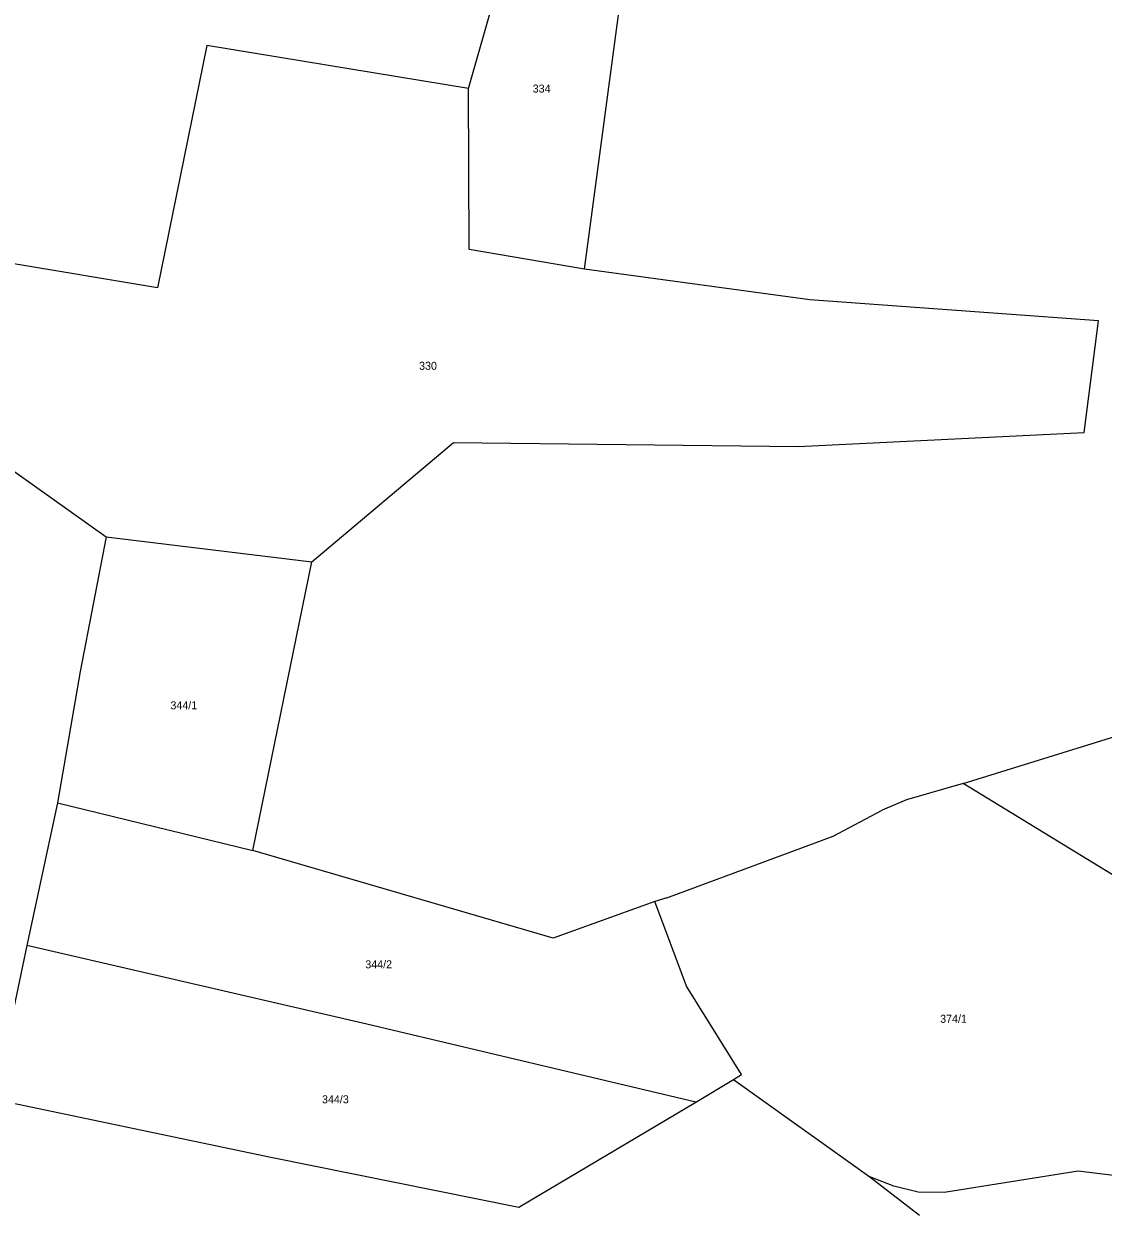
# Model space of a CAD drawing. Extents: x -791548 to -789311, y -1142631 to -1140855.
# Drawn here: x -790982.6 to -790753.3, y -1142211.2 to -1141959 of the extents above; entities that cross this region are included whole.
import ezdxf
from ezdxf.enums import TextEntityAlignment as Align

# ---------------------------------------------------------------- set-up
doc = ezdxf.new("R2010")
doc.units = 0
doc.header["$LTSCALE"] = 0.68
doc.layers.add('1', color=7, linetype='Continuous', lineweight=25)
doc.layers.add('2', color=7, linetype='Continuous')

msp = doc.modelspace()

# ---------------------------------------------------------------- linework, layer by layer
at = {"layer": '1'}
for p, q in [((-790888.15, -1141972.78), (-790875.94, -1141930.15)), ((-790863.48, -1142011.16), (-790853.52, -1141936.36)), ((-790943.74, -1141963.65), (-790954.25, -1142015.12)), ((-790888.15, -1141972.78), (-790943.74, -1141963.65)), ((-790887.96, -1142006.94), (-790888.15, -1141972.78)), ((-790863.48, -1142011.16), (-790887.96, -1142006.94)), ((-790954.25, -1142015.12), (-790985.61, -1142009.88)), ((-790815.6, -1142017.65), (-790863.48, -1142011.16)), ((-790754.26, -1142022.12), (-790815.6, -1142017.65)), ((-790757.29, -1142045.83), (-790754.26, -1142022.12)), ((-790818.07, -1142048.8), (-790757.29, -1142045.83)), ((-790994.07, -1142047.46), (-790965.09, -1142067.97)), ((-790921.39, -1142073.27), (-790891.29, -1142047.92)), ((-790891.29, -1142047.92), (-790818.07, -1142048.8)), ((-790965.09, -1142067.97), (-790970.68, -1142096.58)), ((-790965.09, -1142067.97), (-790921.39, -1142073.27)), ((-790933.96, -1142134.58), (-790921.39, -1142073.27)), ((-790970.68, -1142096.58), (-790975.45, -1142124.47)), ((-790783.03, -1142120.37), (-790726.36, -1142102.85)), ((-790783.03, -1142120.37), (-790795.07, -1142123.83)), ((-790750.26, -1142140.45), (-790783.03, -1142120.37)), ((-790975.45, -1142124.47), (-790981.99, -1142154.78)), ((-790975.45, -1142124.47), (-790933.96, -1142134.58)), ((-790795.07, -1142123.83), (-790800.24, -1142126.07)), ((-790810.64, -1142131.54), (-790800.24, -1142126.07)), ((-790845.97, -1142144.69), (-790810.64, -1142131.54)), ((-790870.15, -1142153.22), (-790933.96, -1142134.58)), ((-790845.97, -1142144.69), (-790848.57, -1142145.44)), ((-790848.57, -1142145.44), (-790870.15, -1142153.22)), ((-790841.8, -1142163.43), (-790848.57, -1142145.44)), ((-790981.99, -1142154.78), (-790988.86, -1142187.43)), ((-790909.71, -1142171.49), (-790981.99, -1142154.78)), ((-790830.16, -1142182.21), (-790841.8, -1142163.43)), ((-790839.81, -1142188.08), (-790909.71, -1142171.49)), ((-790831.84, -1142183.23), (-790830.16, -1142182.21)), ((-790839.81, -1142188.08), (-790831.84, -1142183.23)), ((-790831.84, -1142183.23), (-790802.84, -1142203.93)), ((-790988.86, -1142187.43), (-790930.11, -1142199.76)), ((-790877.41, -1142210.38), (-790839.81, -1142188.08)), ((-790930.11, -1142199.76), (-790877.41, -1142210.38)), ((-790758.58, -1142202.74), (-790787.04, -1142207.24)), ((-790737, -1142205.34), (-790758.58, -1142202.74)), ((-790797.78, -1142205.94), (-790802.84, -1142203.93)), ((-790802.84, -1142203.93), (-790792.31, -1142212.1)), ((-790792.56, -1142207.19), (-790797.78, -1142205.94)), ((-790787.04, -1142207.24), (-790792.56, -1142207.19))]:
    msp.add_line(p, q, dxfattribs=at)

# ---------------------------------------------------------------- texts
at = {"layer": '2'}
for s, p in [('334', (-790872.599, -1141973.622)), ('330', (-790896.739, -1142032.502)), ('344/1', (-790948.63, -1142104.622)), ('344/2', (-790907.22, -1142159.642)), ('374/1', (-790785.08, -1142171.212)), ('344/3', (-790916.42, -1142188.312))]:
    msp.add_text(s, height=1.7, dxfattribs=at).set_placement(p, align=Align.CENTER)

doc.saveas('drawing.dxf')
